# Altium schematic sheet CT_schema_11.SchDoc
size 274 x 160 mm
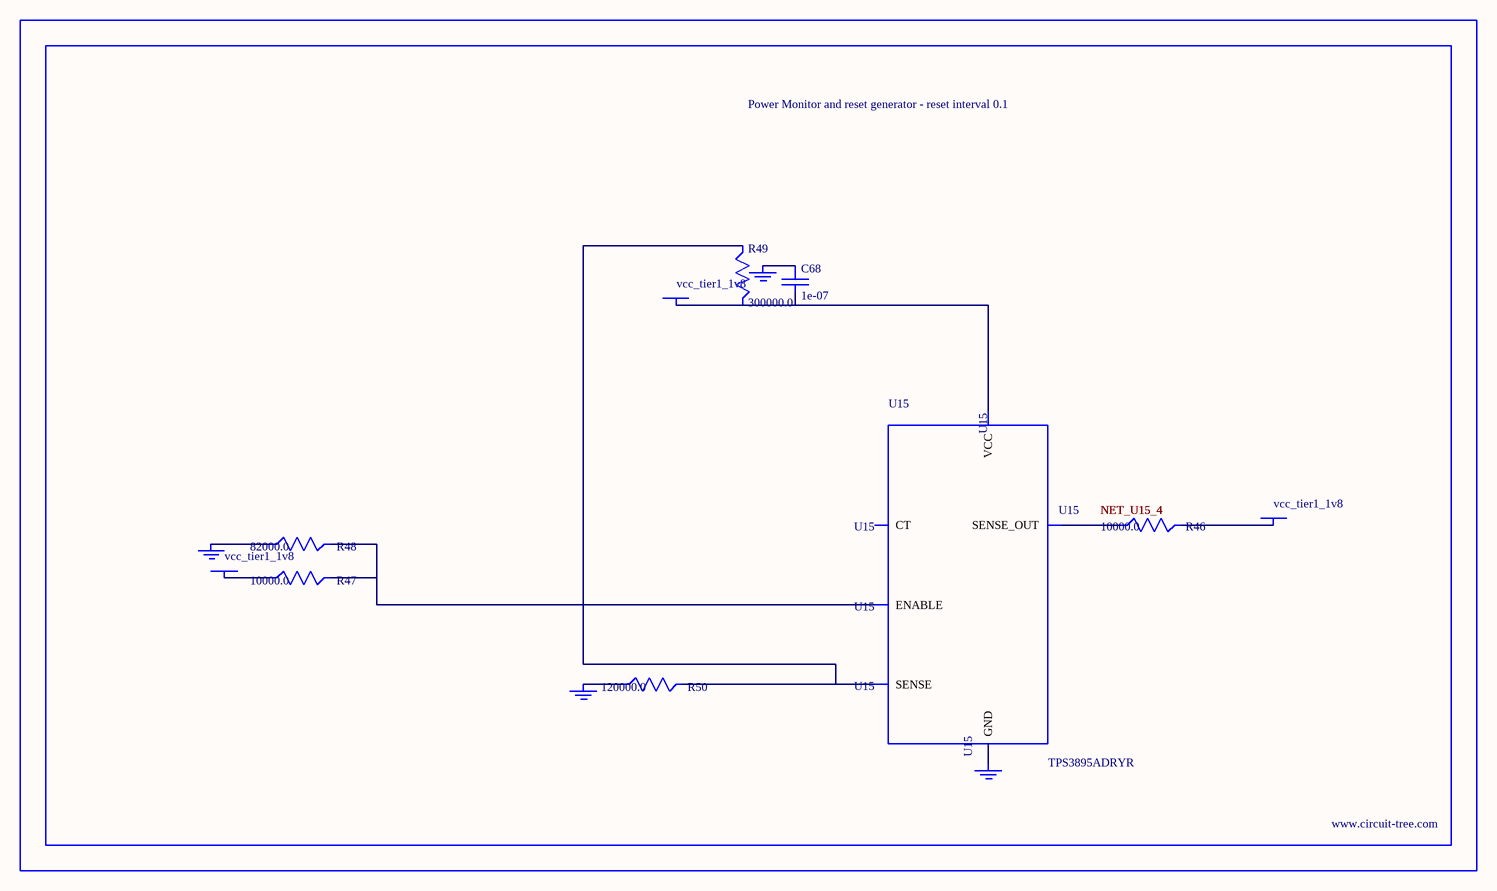
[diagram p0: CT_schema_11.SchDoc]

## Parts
BORDER10  (no value)
C68  1e-07  [C0402]
GND_INSTANCE_10_0  (no value)
GND_INSTANCE_10_1  (no value)
GND_INSTANCE_10_2  (no value)
GND_INSTANCE_10_3  (no value)
POWER_INSTANCE_10_0  vcc_tier1_1v8
POWER_INSTANCE_10_1  vcc_tier1_1v8
POWER_INSTANCE_10_2  vcc_tier1_1v8
R46  10000.0  [R0603]
R47  10000.0  [R0603]
R48  82000.0  [R0603]
R49  300000.0  [R0603]
R50  120000.0  [R0603]
U15  TPS3895ADRYR  [SON-6]

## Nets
NetC68_1: C68.1 GND_INSTANCE_10_2.0(GND)
NetC68_2: C68.2 POWER_INSTANCE_10_2.0(PWR) R49.2 U15.6(VCC)
NetGND_INSTANCE_10_0_0: GND_INSTANCE_10_0.0(GND) R48.1
NetGND_INSTANCE_10_1_0: GND_INSTANCE_10_1.0(GND) R50.1
NetGND_INSTANCE_10_3_0: GND_INSTANCE_10_3.0(GND) U15.2(GND)
NetPOWER_INSTANCE_10_0_0: POWER_INSTANCE_10_0.0(PWR) R47.1
NetPOWER_INSTANCE_10_1_0: POWER_INSTANCE_10_1.0(PWR) R46.2
NetR46_1: R46.1 U15.4(SENSE_OUT)
NetR47_2: R47.2 R48.2 U15.1(ENABLE)
NetR49_1: R49.1 R50.2 U15.3(SENSE)

Not connected (* = marked no-connect by the designer): U15 5(CT)

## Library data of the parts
BORDER10 = BORDER_PAGE10
C68 = C0402C104K3RACTU
GND_INSTANCE_10_0-GND_INSTANCE_10_3 = GND
POWER_INSTANCE_10_0-POWER_INSTANCE_10_2 = PWR
R46 R47 = RC0603JR-0710KL
R48 = RC0603JR-0782KL
R49 = RC0603JR-07300KL
R50 = RC0603JR-07120KL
